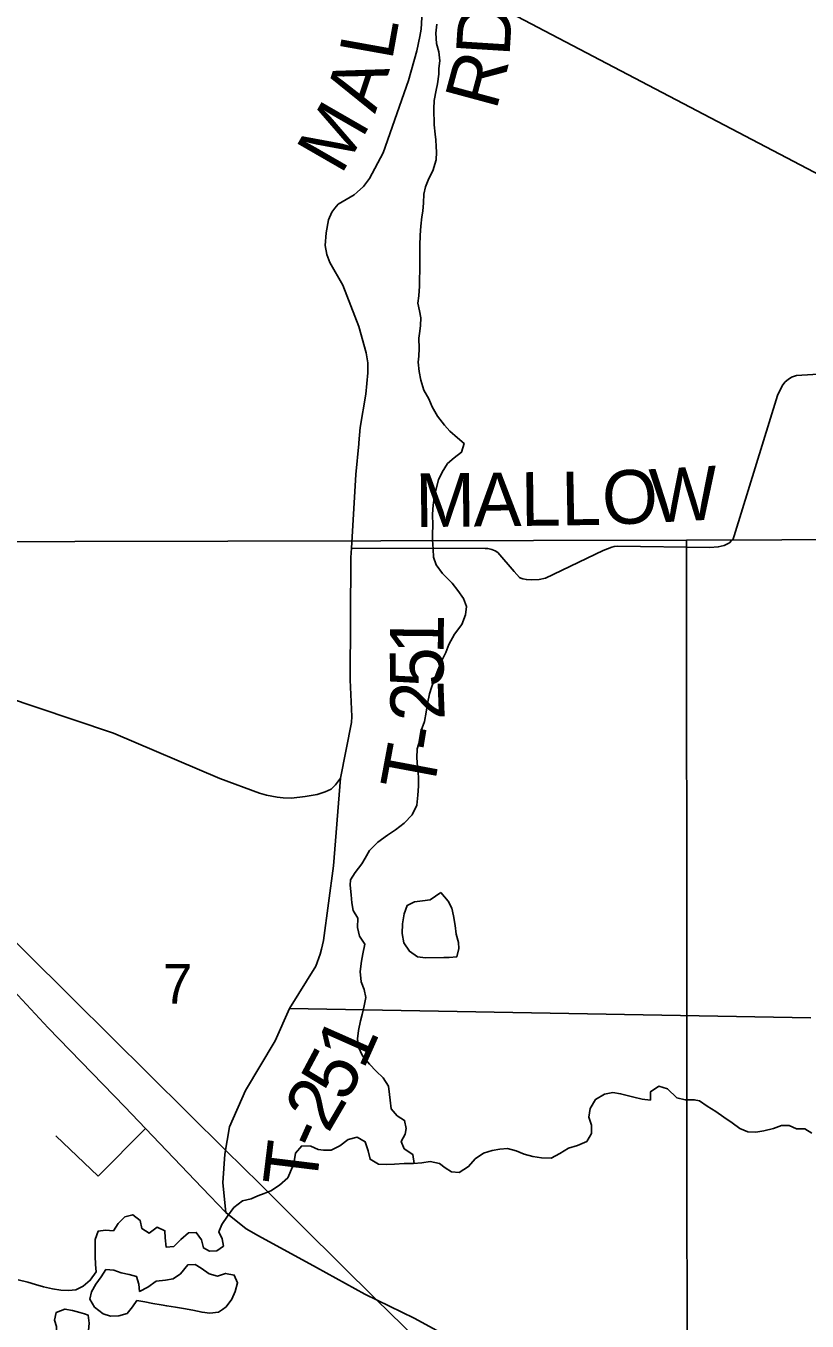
# Model space of a CAD drawing. Extents: x 0 to 34, y 0 to 22.
# Drawn here: x 6.566 to 7.392, y 15.175 to 16.545 of the extents above; entities that cross this region are included whole.
import ezdxf

# ---------------------------------------------------------------- set-up
doc = ezdxf.new("R2010")
doc.units = 0
doc.layers.add('Default', color=7, linetype='Continuous')
doc.layers.add('SH_Text', color=7, linetype='Continuous')

msp = doc.modelspace()

# ---------------------------------------------------------------- linework, layer by layer
at = {"layer": 'Default'}
for p, q in [((6.5977, 15.3712), (6.6425, 15.3286)), ((6.6425, 15.3286), (6.6928, 15.3789))]:
    msp.add_line(p, q, dxfattribs=at)
for points in [[(6.9183, 16.1044), (6.9199, 16.1207), (6.9256, 16.1557), (6.928, 16.1782), (6.9279, 16.1889), (6.9262, 16.1995), (6.9183, 16.2272), (6.9015, 16.2711), (6.8875, 16.2949), (6.8844, 16.3034), (6.8827, 16.3132), (6.8837, 16.3265), (6.8862, 16.3402), (6.8897, 16.3482), (6.8929, 16.3524), (6.8965, 16.3567), (6.9134, 16.3667), (6.9167, 16.3695), (6.9232, 16.3756), (6.9295, 16.384), (6.9441, 16.4112), (6.971, 16.4875), (6.9795, 16.5188), (6.9829, 16.5342), (6.9842, 16.5417), (6.9856, 16.5666)], [(6.982, 16.2042), (6.9818, 16.2149), (6.9828, 16.2225), (6.9835, 16.2286), (6.9838, 16.2365), (6.9825, 16.2441), (6.9809, 16.2521), (6.9819, 16.2597), (6.9825, 16.2699), (6.9824, 16.2787), (6.9827, 16.2851), (6.9829, 16.2946), (6.9827, 16.3132), (6.9833, 16.3239), (6.9839, 16.3334), (6.9849, 16.3432), (6.9859, 16.3493), (6.9866, 16.3581), (6.9872, 16.3672), (6.989, 16.3752), (6.9923, 16.384), (6.9967, 16.392), (7, 16.4038), (7.0006, 16.4118), (7.0001, 16.4179), (6.9997, 16.4247), (6.9992, 16.4308), (6.9979, 16.4406), (6.9977, 16.4577), (6.9979, 16.4664), (7, 16.4775), (7.0014, 16.484), (7.0028, 16.4942), (7.0031, 16.5003), (7.0041, 16.5083), (7.0029, 16.5178), (7.0004, 16.5268), (6.9999, 16.5378), (7.0009, 16.547)], [(6.9767, 15.3422), (6.9753, 15.3517), (6.9661, 15.3576), (6.963, 15.3652), (6.9674, 15.3732), (6.9685, 15.3789), (6.9668, 15.3876), (6.9588, 15.3925), (6.9526, 15.4), (6.9513, 15.4091), (6.9509, 15.4151), (6.9496, 15.4238), (6.9442, 15.4325), (6.9365, 15.4396), (6.9295, 15.4471), (6.9222, 15.4561), (6.9179, 15.4652), (6.917, 15.4739), (6.918, 15.4826), (6.9201, 15.4929), (6.9219, 15.4998), (6.9241, 15.5089), (6.9259, 15.5177), (6.9238, 15.526), (6.9207, 15.5343), (6.9198, 15.5453), (6.9211, 15.556), (6.9225, 15.564), (6.9246, 15.5742), (6.9192, 15.5825), (6.9168, 15.5916), (6.9174, 15.6015), (6.9124, 15.6098), (6.9111, 15.6177), (6.9102, 15.6264), (6.9093, 15.6363), (6.9096, 15.642), (6.9144, 15.65), (6.9215, 15.6589), (6.9252, 15.665), (6.9297, 15.673), (6.9383, 15.6819), (6.9488, 15.6893), (6.9571, 15.6951), (6.9661, 15.702), (6.9747, 15.7109), (6.9795, 15.7212), (6.9809, 15.7315), (6.9815, 15.741), (6.9813, 15.7509), (6.9804, 15.7615), (6.9795, 15.771), (6.9801, 15.7808), (6.9827, 15.79), (6.9844, 15.7999), (6.9877, 15.8094), (6.9895, 15.8193), (6.9908, 15.8285), (6.993, 15.8387), (6.9951, 15.8456), (6.9992, 15.8563), (7.001, 15.862), (7.0061, 15.8742), (7.0102, 15.8827), (7.0135, 15.8911), (7.0194, 15.9018), (7.0272, 15.9121), (7.0313, 15.9224), (7.0323, 15.9312), (7.0291, 15.9395), (7.0229, 15.9481), (7.0171, 15.956), (7.0067, 15.9661), (7.0001, 15.9752), (6.9973, 15.9835), (6.9968, 15.9918), (6.9963, 16.0017), (6.9962, 16.0081), (6.9965, 16.0169), (6.9963, 16.029), (6.9969, 16.0385), (6.9983, 16.048), (6.9997, 16.0541), (7.0026, 16.0652), (7.0063, 16.0732), (7.0122, 16.0824), (7.0193, 16.0886), (7.0269, 16.0944), (7.0298, 16.1035), (7.0228, 16.1095), (7.0144, 16.1166), (7.009, 16.123), (7.0016, 16.1324), (6.9958, 16.1425), (6.9922, 16.1508), (6.9872, 16.1599), (6.984, 16.1705), (6.9823, 16.1796), (6.981, 16.1898), (6.9817, 16.1959), (6.982, 16.2042)], [(7.536, 16.1851), (7.3811, 16.1756), (7.3759, 16.1738), (7.3724, 16.1713), (7.3693, 16.1687), (7.3669, 16.1656), (7.3643, 16.1611), (7.3612, 16.1544), (7.3154, 16.006), (7.3141, 16.0029), (7.3124, 16.001), (7.3103, 15.9987), (7.3047, 15.9956), (7.2984, 15.9942), (7.2895, 15.9935), (7.1918, 15.9949), (7.1882, 15.9945), (7.1858, 15.9939), (7.1768, 15.9905), (7.1158, 15.9613), (7.1089, 15.9598), (7.1006, 15.9593), (7.0955, 15.9596), (7.0917, 15.9603), (7.0895, 15.9611), (7.0884, 15.962), (7.0826, 15.9682), (7.0654, 15.9883), (7.0626, 15.99), (7.059, 15.9914), (7.0547, 15.9926), (7.052, 15.9926), (6.9105, 15.9929)], [(6.8988, 15.7495), (6.9107, 15.8086), (6.9109, 15.815), (6.9091, 15.8535), (6.9099, 15.9832), (6.9105, 15.9929), (6.9151, 16.0708), (6.9182, 16.1034), (6.9183, 16.1044)], [(6.8988, 15.7495), (6.8938, 15.7425), (6.889, 15.738), (6.8826, 15.7351), (6.8742, 15.7325), (6.8615, 15.7302), (6.8472, 15.7284), (6.8382, 15.7287), (6.832, 15.7294), (6.8206, 15.7316), (6.8131, 15.7338), (6.7712, 15.7494), (6.6588, 15.7973), (6.616, 15.8117), (6.5078, 15.8479), (6.4443, 15.8724), (6.4082, 15.8968)], [(6.8451, 15.506), (6.8727, 15.5509), (6.8775, 15.5635), (6.879, 15.5687), (6.8809, 15.5781), (6.8914, 15.657), (6.8988, 15.7495)], [(6.8451, 15.506), (6.8727, 15.5509), (6.8775, 15.5635), (6.879, 15.5687), (6.8809, 15.5781), (6.8914, 15.657), (6.8988, 15.7495)], [(6.9791, 15.1568), (6.9366, 15.1982), (6.8602, 15.2739), (6.8136, 15.3204), (6.7775, 15.3558), (6.6156, 15.5167), (6.41, 15.7203)], [(7.0051, 15.6286), (6.9939, 15.6208), (6.9855, 15.6199), (6.9772, 15.6187), (6.9696, 15.6151), (6.9663, 15.606), (6.9646, 15.5957), (6.964, 15.5854), (6.966, 15.5756), (6.9719, 15.5666), (6.9803, 15.5606), (6.989, 15.5596), (7.0081, 15.5599)], [(7.0081, 15.5599), (7.0137, 15.5599), (7.0221, 15.5608), (7.0242, 15.5696), (7.0238, 15.5757), (7.0213, 15.5847), (7.0201, 15.5938), (7.0184, 15.6041), (7.0168, 15.612), (7.0129, 15.6195), (7.0051, 15.6286)], [(6.5394, 15.5399), (6.5899, 15.4855), (6.6708, 15.4021), (6.6928, 15.3789), (6.7527, 15.3164), (6.7777, 15.2904), (6.7991, 15.2728), (6.8123, 15.2654), (6.8735, 15.2322), (6.9245, 15.2039), (6.9768, 15.1783), (7.032, 15.1484), (7.0474, 15.1405), (7.0639, 15.1301), (7.0941, 15.1014), (7.1046, 15.0944), (7.1157, 15.0892), (7.1244, 15.0858), (7.1323, 15.083), (7.1403, 15.0815), (7.1549, 15.078)], [(6.7777, 15.2904), (6.7744, 15.3217), (6.7767, 15.3518), (6.7814, 15.3808), (6.7985, 15.4194), (6.8299, 15.4718), (6.8451, 15.506)], [(7.3962, 15.4962), (6.8451, 15.506)], [(7.0931, 15.3518), (7.1022, 15.3493), (7.1114, 15.3479), (7.1216, 15.3477), (7.131, 15.3527), (7.1401, 15.3582), (7.1495, 15.361), (7.1593, 15.3653), (7.1645, 15.3737), (7.1644, 15.3825), (7.1616, 15.3912), (7.163, 15.4003), (7.1686, 15.4099), (7.178, 15.4153), (7.1871, 15.417), (7.1951, 15.4159), (7.2034, 15.4138), (7.2092, 15.4123), (7.2179, 15.4102), (7.2267, 15.4092), (7.2269, 15.4179), (7.2356, 15.4237), (7.2447, 15.4212), (7.2548, 15.4115), (7.2635, 15.4093), (7.273, 15.4094), (7.2787, 15.4084), (7.2868, 15.4028), (7.296, 15.3969), (7.3044, 15.3909), (7.3132, 15.385), (7.3213, 15.379), (7.3297, 15.3757), (7.3381, 15.3751), (7.3468, 15.3767), (7.357, 15.3791), (7.3653, 15.3823), (7.3733, 15.3824), (7.3813, 15.3787), (7.39, 15.3788), (7.3973, 15.374)], [(6.558, 15.2189), (6.5683, 15.2164), (6.5763, 15.2139), (6.5847, 15.2117), (6.5942, 15.2096), (6.603, 15.2082), (6.6113, 15.2079), (6.6189, 15.2084), (6.6268, 15.2123), (6.6343, 15.2185), (6.6407, 15.2273), (6.6398, 15.2353), (6.6393, 15.244), (6.6395, 15.2527), (6.6394, 15.2618), (6.6427, 15.2706), (6.6503, 15.2715), (6.6587, 15.2709), (6.6639, 15.2785), (6.671, 15.2855), (6.6793, 15.2879), (6.687, 15.2819), (6.689, 15.2732), (6.6967, 15.2684), (6.7049, 15.2746), (6.7133, 15.2709), (6.7135, 15.2633), (6.7147, 15.2534), (6.7227, 15.2543), (6.7302, 15.2616), (6.7381, 15.2686), (6.7464, 15.2691), (6.7518, 15.2612), (6.7539, 15.2528), (6.7604, 15.2495), (6.7683, 15.2496), (6.7751, 15.2547), (6.7738, 15.2622), (6.7703, 15.2698), (6.7736, 15.2774), (6.7796, 15.2862), (6.7863, 15.2955), (6.7953, 15.3024), (6.8044, 15.3048), (6.8115, 15.308), (6.8183, 15.3103), (6.8251, 15.3131), (6.8345, 15.3193), (6.8432, 15.327), (6.8483, 15.3385), (6.8498, 15.3442), (6.8515, 15.353), (6.8582, 15.3607), (6.8674, 15.3604), (6.8754, 15.3567), (6.8811, 15.356), (6.8891, 15.3562), (6.8981, 15.3608), (6.9071, 15.3674), (6.9166, 15.3698), (6.925, 15.365), (6.9282, 15.3556), (6.9302, 15.3465), (6.939, 15.3413), (6.9474, 15.341), (6.9561, 15.3412), (6.9664, 15.3421), (6.9762, 15.3422), (6.985, 15.3427), (6.9937, 15.344), (7.0036, 15.3422), (7.0097, 15.3374), (7.0162, 15.3333), (7.0246, 15.3326), (7.0344, 15.3388), (7.0415, 15.3469), (7.0501, 15.3531), (7.0592, 15.3559), (7.0676, 15.3572), (7.0755, 15.358), (7.0847, 15.3555), (7.0931, 15.3518)], [(6.7742, 15.1878), (6.7779, 15.1905), (6.7839, 15.1986), (6.7876, 15.2066), (6.7901, 15.2158), (6.7866, 15.2241), (6.7774, 15.2258), (6.7687, 15.223), (6.76, 15.2252), (6.7515, 15.2315), (6.7454, 15.2352), (6.7374, 15.2348), (6.7296, 15.2252), (6.722, 15.2201), (6.7137, 15.2188), (6.7039, 15.2176), (6.6952, 15.2114), (6.6865, 15.2067), (6.6857, 15.2143), (6.6833, 15.2226), (6.6753, 15.2248), (6.6669, 15.2265), (6.6593, 15.2291), (6.6509, 15.2301)], [(6.6509, 15.2301), (6.6457, 15.2221), (6.6401, 15.2144), (6.6357, 15.2064), (6.6339, 15.1984), (6.6386, 15.1901), (6.6478, 15.183), (6.6558, 15.1804), (6.6645, 15.1809), (6.6732, 15.1833), (6.6788, 15.1906), (6.6836, 15.1972), (6.692, 15.1958), (6.7004, 15.194), (6.7092, 15.1926), (6.7152, 15.1915), (6.7244, 15.1901), (6.7328, 15.1887), (6.7427, 15.187), (6.7526, 15.1848), (6.7609, 15.1838), (6.77, 15.1847), (6.7742, 15.1878)], [(6.6281, 15.183), (6.6234, 15.1845), (6.6154, 15.1867), (6.6074, 15.1881), (6.5984, 15.1846), (6.5966, 15.1762), (6.5986, 15.1697), (6.5991, 15.1603), (6.5981, 15.1519), (6.5972, 15.1373)], [(6.5972, 15.1373), (6.6131, 15.1358), (6.6222, 15.1363), (6.6302, 15.141), (6.6312, 15.1493), (6.6322, 15.1573), (6.6325, 15.1653), (6.6331, 15.1733), (6.6322, 15.1816), (6.6281, 15.183)]]:
    msp.add_lwpolyline(points, dxfattribs=at)
for points in [[(6.2943, 15.9991), (7.265, 16.0012), (7.2656, 14.9873), (6.2908, 15.0024), (6.2933, 15.4392)], [(8.2726, 16.0048), (8.2795, 14.9973), (7.2656, 14.9873), (7.265, 16.0012)]]:
    msp.add_lwpolyline(points, close=True, dxfattribs=at)
at = {"layer": 'SH_Text'}
msp.add_lwpolyline([(5.6822, 17.291), (7.4073, 16.9867), (7.4073, 16.3867)], close=True, dxfattribs=at)

# ---------------------------------------------------------------- texts
at = {"layer": 'Default'}
for s, height, rotation, p in [('D', 0.0568, 86.4106, (7.0776, 16.5123)), ('L', 0.0568, 79.8001, (6.9534, 16.5078)), ('R', 0.0568, 74.8931, (7.0635, 16.4551)), ('A', 0.0568, 71.6673, (6.9355, 16.4518)), ('M', 0.0568, 60.0555, (6.8996, 16.3869)), ('M', 0.0568, 0.6734, (6.9783, 16.0151)), ('A', 0.0568, 0.6703, (7.0399, 16.0158)), ('L', 0.0568, 0.6696, (7.0899, 16.0164)), ('L', 0.0568, 0.993, (7.1328, 16.0169)), ('O', 0.0568, 2.2376, (7.1766, 16.0176)), ('W', 0.0568, 3.1423, (7.2275, 16.0196)), ('1', 0.0568, 89.3651, (7.0079, 15.8806)), ('5', 0.0568, 90.1665, (7.008, 15.8458)), ('2', 0.0568, 92.1612, (7.0093, 15.8113)), ('-', 0.0568, 80.5694, (7.0047, 15.7758)), ('T', 0.0568, 79.4103, (6.9967, 15.7328)), ('7', 0.0419, 0, (6.711, 15.5112)), ('1', 0.0568, 66.0458, (6.9232, 15.4403)), ('5', 0.0568, 61.9159, (6.9047, 15.4054)), ('2', 0.0568, 59.6619, (6.8859, 15.3731)), ('-', 0.0568, 65.8513, (6.8771, 15.3533)), ('T', 0.0568, 83.027, (6.8731, 15.3154))]:
    msp.add_text(s, height=height, rotation=rotation, dxfattribs=at).set_placement(p)

doc.saveas('drawing.dxf')
